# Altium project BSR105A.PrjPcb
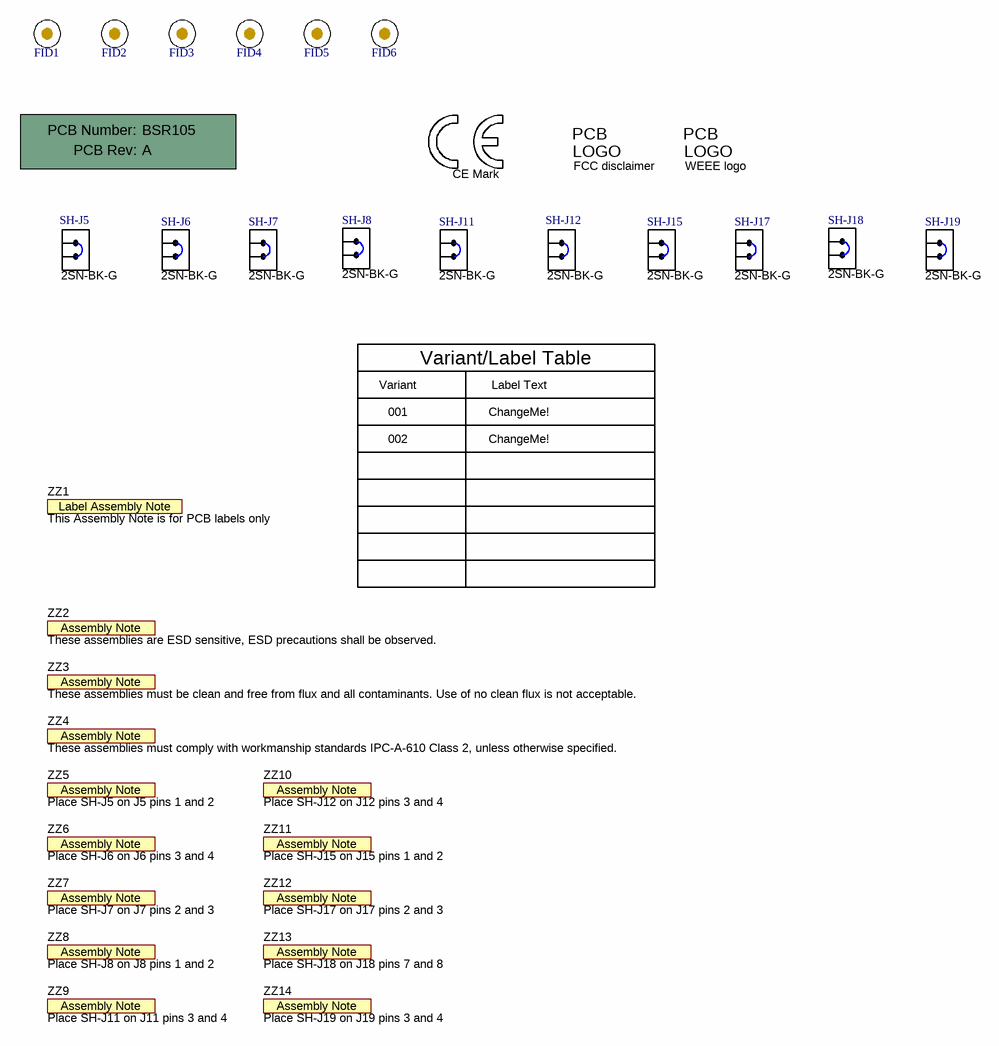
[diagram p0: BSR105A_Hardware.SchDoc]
CopyrightYear: 2019; EVM_Orderable: TPSM5D1806EVM; PCB_Layout: Jim McTeague; PCB_Rev: A; PRJ_Customer: Public Release; PRJ_Engineer: Jason Arrigo; PRJ_Number: BSR105; PRJ_Title: TPSM5D1806EVM; SCH_Rev: A; TechSupport: http://www.ti.com/support; TID: N/A
3 sheets, 167 parts. Net scope: global (net labels, ports and power ports of the same name join across sheets).
Board file: BSR105A.PcbDoc
Sheets:
  BSR105A_Hardware.SchDoc
  BSR105A_SHT2.schdoc
  BSR105A_SHT1.schdoc

## Sheet BSR105A_Hardware.SchDoc
size 431 x 279 mm; Date: Not shown in title block; ApprovedBy: Not shown in title block; CheckedBy: Not shown in title block; Author: Not shown in title block; CompanyName: Not shown in title block; Engineer: Not shown in title block; Organization: Not shown in title block; Address1: Not shown in title block; Address2: Not shown in title block; Address3: Not shown in title block; Address4: Not shown in title block; DocumentNumber: 3; Revision: Use project parameter SCH_Rev; SheetNumber: 3; SheetTotal: 3; PageSetup: Record=PageOptions¦CenterHorizontal=True¦CenterVertical=True¦PrintScale=1.00¦XCorrection=1.00¦YCorrection=1.00¦PrintKind=0¦BorderSize=5000000¦LeftOffset=0¦BottomOffset=0¦Orientation=2¦PaperLength=1000¦PaperWidth=1000¦Scale=100¦PaperSource=15¦PrintQuality=600¦MediaType=1¦DitherType=10¦PaperKind=Letter¦PrintScaleMode=1

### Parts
!PCB1  Printed Circuit Board  (value not drawn)  (mechanical)
FID1  Fiducial  [Fiducial10-30]  (value not drawn)
FID2  Fiducial  [Fiducial10-30]  (value not drawn)
FID3  Fiducial  [Fiducial10-30]  (value not drawn)
FID4  Fiducial  [Fiducial10-30]  (value not drawn)
FID5  Fiducial  [Fiducial10-30]  (value not drawn)
FID6  Fiducial  [Fiducial10-30]  (value not drawn)
Logo1  CE Mark  [CE_Mark_5mm]  (no BOM)
Logo3  FCC disclaimer  [FCC_disclaimer]  (no BOM)
Logo4  WEEE logo  [WEEE_Minimum]  (no BOM)
SH-J5  2SN-BK-G  [2SN-BK-G]
SH-J6  2SN-BK-G  [2SN-BK-G]
SH-J7  2SN-BK-G  [2SN-BK-G]
SH-J8  2SN-BK-G  [2SN-BK-G]
SH-J11  2SN-BK-G  [2SN-BK-G]
SH-J12  2SN-BK-G  [2SN-BK-G]
SH-J15  2SN-BK-G  [2SN-BK-G]
SH-J17  2SN-BK-G  [2SN-BK-G]
SH-J18  2SN-BK-G  [2SN-BK-G]
SH-J19  2SN-BK-G  [2SN-BK-G]
ZZ1  This Assembly Note is for PCB labels only  [AssemblyNoteLabel]  (no BOM)
ZZ2  These assemblies are ESD sensitive, ESD precautions shall be observed.  [AssemblyNote]  (no BOM)
ZZ3  These assemblies must be clean and free from flux and all contaminants. Use of no clean flux is not acceptable.  [AssemblyNote]  (no BOM)
ZZ4  These assemblies must comply with workmanship standards IPC-A-610 Class 2, unless otherwise specified.  [AssemblyNote]  (no BOM)
ZZ5  Place SH-J5 on J5 pins 1 and 2  [AssemblyNote]  (no BOM)
ZZ6  Place SH-J6 on J6 pins 3 and 4  [AssemblyNote]  (no BOM)
ZZ7  Place SH-J7 on J7 pins 2 and 3  [AssemblyNote]  (no BOM)
ZZ8  Place SH-J8 on J8 pins 1 and 2  [AssemblyNote]  (no BOM)
ZZ9  Place SH-J11 on J11 pins 3 and 4  [AssemblyNote]  (no BOM)
ZZ10  Place SH-J12 on J12 pins 3 and 4  [AssemblyNote]  (no BOM)
ZZ11  Place SH-J15 on J15 pins 1 and 2  [AssemblyNote]  (no BOM)
ZZ12  Place SH-J17 on J17 pins 2 and 3  [AssemblyNote]  (no BOM)
ZZ13  Place SH-J18 on J18 pins 7 and 8  [AssemblyNote]  (no BOM)
ZZ14  Place SH-J19 on J19 pins 3 and 4  [AssemblyNote]  (no BOM)

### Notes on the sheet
- Variant
- Variant/Label Table
- Label Text
- 001
- 002
- ChangeMe!

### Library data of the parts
!PCB1 = CMP-0003618-2: Manufacturer: Any; PartNumber: BSR105
FID1-FID6 = CMP-0077181-1: Fiducial mark.  There is nothing to buy or mount.
Logo1 = CMP-0074844-1: SymbolCreator: a0412235
Logo3 = CMP-0074847-1: FCC_disclaimer
Logo4 = CMP-0074769-1
SH-J5-SH-J8 SH-J11 SH-J12 SH-J15 SH-J17-SH-J19 = CMP-0003641-1: Shunt, 2mm, Gold plated, Black; Manufacturer: Samtec; Value: 1x2
ZZ1 = CMP-0003616-3
ZZ2 = CMP-0077236-1
ZZ3 = CMP-0077237-1
ZZ4 = CMP-0077238-1
ZZ5-ZZ14 = CMP-0003615-1: This Assembly Note will show in the PcbDoc and associated outputs

## Sheet BSR105A_SHT2.schdoc: TPSM5D1806 APL EVM Board
size 431 x 279 mm; REV: A; Number: TPSM5D1806 APL EVM Board; Date: Not shown in title block; ApprovedBy: Not shown in title block; CheckedBy: Not shown in title block; Author: Not shown in title block; CompanyName: Not shown in title block; DrawnBy: Jason Arrigo; Engineer: Not shown in title block; Organization: Not shown in title block; Address1: Not shown in title block; Address2: Not shown in title block; Address3: Not shown in title block; Address4: Not shown in title block; DocumentNumber: 1; Revision: Use project parameter SCH_Rev; SheetNumber: 2; SheetTotal: 3; PageSetup: Record=PageOptions¦CenterHorizontal=True¦CenterVertical=True¦PrintScale=0.96¦XCorrection=1.00¦YCorrection=1.00¦PrintKind=0¦BorderSize=5000000¦LeftOffset=0¦BottomOffset=0¦Orientation=2¦PaperLength=4318¦PaperWidth=2794¦Scale=100¦PaperSource=15¦PrintQuality=600¦MediaType=1¦DitherType=10¦PrintScaleMode=1¦PaperKind=Tabloid (11 x 17")¦PaperIndex=17
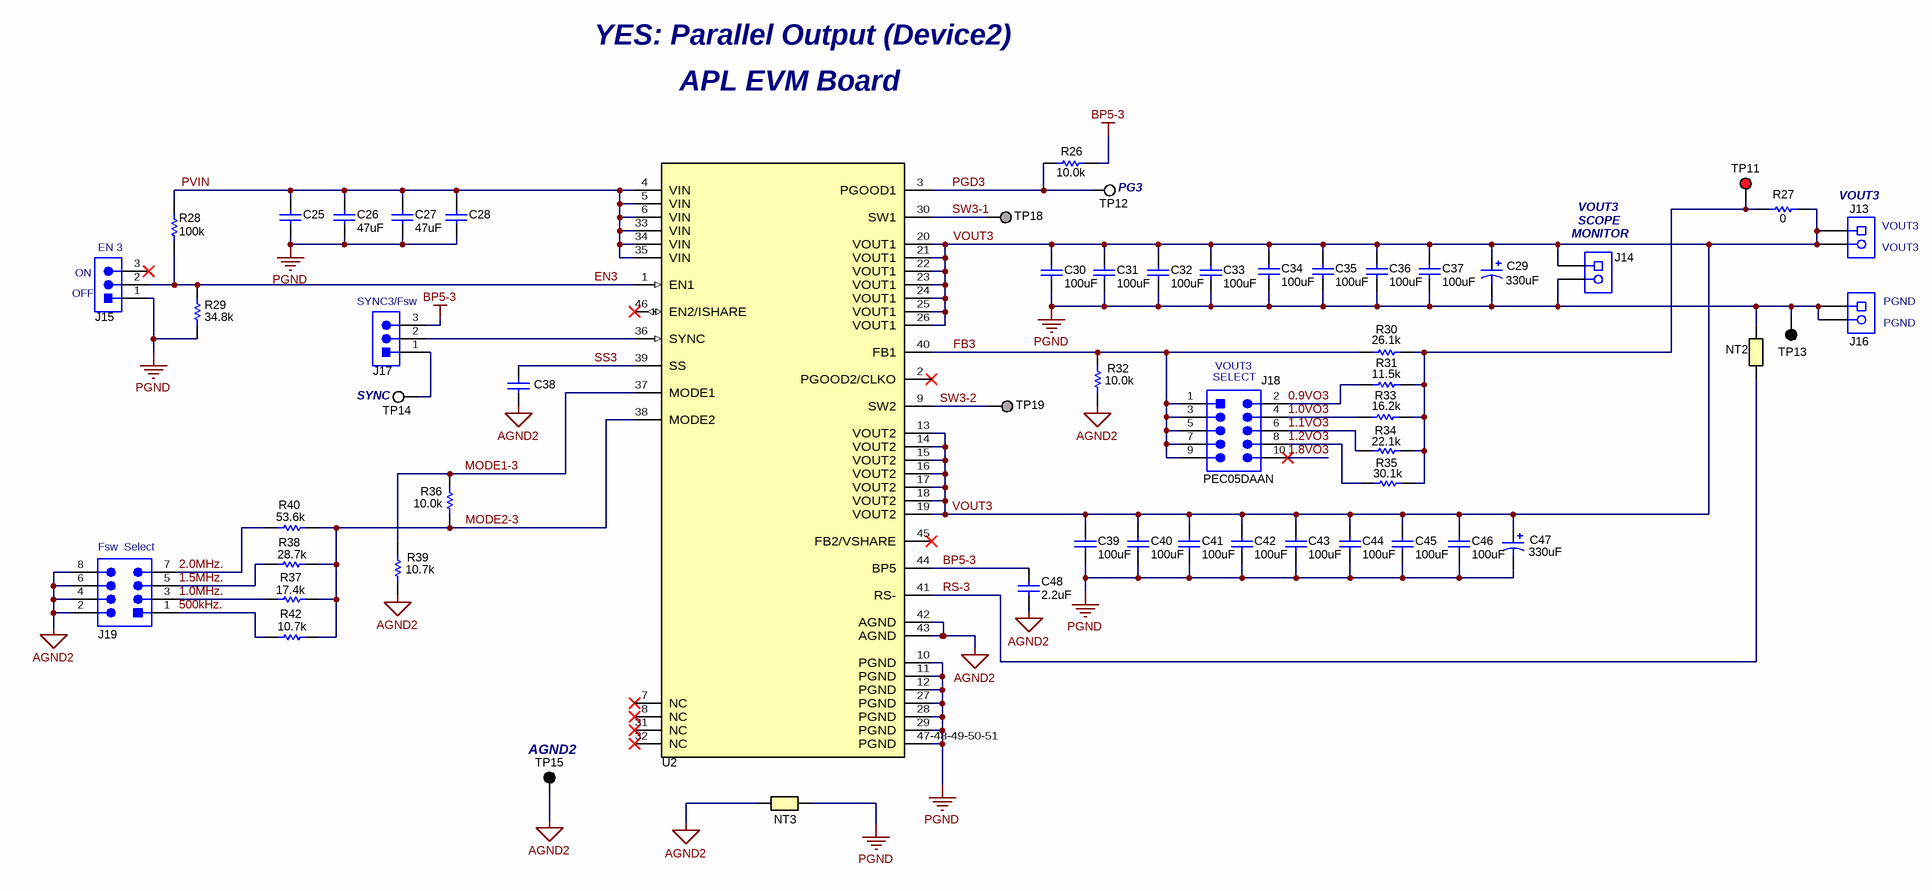
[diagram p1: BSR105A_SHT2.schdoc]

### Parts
C25  C3216X5R1E476M160AC  [1206_190]  (value not drawn)
C26  ValueDisplayed: 47uF  [1206_190]  (hidden comment: C3216X5R1E476M160AC)
C27  ValueDisplayed: 47uF  [1206_190]  (hidden comment: C3216X5R1E476M160AC)
C28  C3216X5R1E476M160AC  [1206_190]  (value not drawn)
C29  ValueDisplayed: 330uF  [7343-40]  (hidden comment: T520Y337M010ATE035)
C30  ValueDisplayed: 100uF  [1206_180]  (hidden comment: GRM31CR60J107ME39L)
C31  ValueDisplayed: 100uF  [1206_180]  (hidden comment: GRM31CR60J107ME39L)
C32  ValueDisplayed: 100uF  [1206_180]  (hidden comment: GRM31CR60J107ME39L)
C33  ValueDisplayed: 100uF  [1206_180]  (hidden comment: GRM31CR60J107ME39L)
C34  ValueDisplayed: 100uF  [1206_180]  (hidden comment: GRM31CR60J107ME39L)
C35  ValueDisplayed: 100uF  [1206_180]  (hidden comment: GRM31CR60J107ME39L)
C36  ValueDisplayed: 100uF  [1206_180]  (hidden comment: GRM31CR60J107ME39L)
C37  ValueDisplayed: 100uF  [1206_180]  (hidden comment: GRM31CR60J107ME39L)
C38  C1608X7R1H473K080AA  [0603]  (value not drawn)
C39  ValueDisplayed: 100uF  [1206_180]  (hidden comment: GRM31CR60J107ME39L)
C40  ValueDisplayed: 100uF  [1206_180]  (hidden comment: GRM31CR60J107ME39L)
C41  ValueDisplayed: 100uF  [1206_180]  (hidden comment: GRM31CR60J107ME39L)
C42  ValueDisplayed: 100uF  [1206_180]  (hidden comment: GRM31CR60J107ME39L)
C43  ValueDisplayed: 100uF  [1206_180]  (hidden comment: GRM31CR60J107ME39L)
C44  ValueDisplayed: 100uF  [1206_180]  (hidden comment: GRM31CR60J107ME39L)
C45  ValueDisplayed: 100uF  [1206_180]  (hidden comment: GRM31CR60J107ME39L)
C46  ValueDisplayed: 100uF  [1206_180]  (hidden comment: GRM31CR60J107ME39L)
C47  ValueDisplayed: 330uF  [7343-40]  (hidden comment: T520Y337M010ATE035)
C48  ValueDisplayed: 2.2uF  [0603]  (hidden comment: C1608X6S1C225K080AC)
J13  ED120/2DS  [On-Shore_ED120_2DS]  (value not drawn)
J14  310-43-102-41-001000  [Mill-max_310-43-102-41-001000]  (value not drawn)
J15  PEC03SAAN  [CONN_PEC03SAAN]  (value not drawn)
J16  ED120/2DS  [On-Shore_ED120_2DS]  (value not drawn)
J17  PEC03SAAN  [CONN_PEC03SAAN]  (value not drawn)
J18  PEC05DAAN  [CONN_PEC05DAAN]
J19  PEC04DAAN  [CONN_PEC04DAAN]  (value not drawn)
NT2  Net-Tie  [Net-Tie_10mil]  (value not drawn)  (net tie, no BOM)
NT3  Net-Tie  [Net-Tie_10mil]  (value not drawn)  (net tie, no BOM)
R26  ValueDisplayed: 10.0k  [0603]  (hidden comment: CRCW060310K0FKEA)
R27  ValueDisplayed: 0  [0603]  (hidden comment: CRCW06030000Z0EA)
R28  ValueDisplayed: 100k  [0603]  (hidden comment: CRCW0603100KFKEA)
R29  ValueDisplayed: 34.8k  [0603]  (hidden comment: CRCW060334K8FKEA)
R30  ValueDisplayed: 26.1k  [0603]  (hidden comment: CRCW060326K1FKEA)
R31  ValueDisplayed: 11.5k  [0603]  (hidden comment: CRCW060311K5FKEA)
R32  ValueDisplayed: 10.0k  [0603]  (hidden comment: CRCW060310K0FKEA)
R33  ValueDisplayed: 16.2k  [0603]  (hidden comment: CRCW060316K2FKEA)
R34  ValueDisplayed: 22.1k  [0603]  (hidden comment: CRCW060322K1FKEA)
R35  ValueDisplayed: 30.1k  [0603]  (hidden comment: CRCW060330K1FKEA)
R36  ValueDisplayed: 10.0k  [0603]  (hidden comment: CRCW060310K0FKEA)
R37  ValueDisplayed: 17.4k  [0603]  (hidden comment: CRCW060317K4FKEA)
R38  ValueDisplayed: 28.7k  [0603]  (hidden comment: CRCW060328K7FKEA)
R39  ValueDisplayed: 10.7k  [0603]  (hidden comment: CRCW060310K7FKEA)
R40  ValueDisplayed: 53.6k  [0603]  (hidden comment: CRCW060353K6FKEA)
R42  ValueDisplayed: 10.7k  [0603]  (hidden comment: CRCW060310K7FKEA)
TP11  5010  [Keystone5010]  (value not drawn)
TP12  5012  [Keystone5012]  (value not drawn)
TP13  5011  [Keystone5011]  (value not drawn)
TP14  5012  [Keystone5012]  (value not drawn)
TP15  5011  [Keystone5011]  (value not drawn)
TP18  TESTPOINT  [TP_25MIL-SMT]  (value not drawn)  (no BOM)
TP19  TESTPOINT  [TP_25MIL-SMT]  (value not drawn)  (no BOM)
U2  TPSM5D1806RDB  [RDB0051A-MFG]  (value not drawn)

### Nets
AGND2: C38.2 C48.2 J19.2 J19.4 J19.6 J19.8 NT3.1 R32.1 R39.1 TP15.1 U2.42(AGND) U2.43(AGND)
BP5-3: C48.1 J17.3 R26.2 U2.44(BP5)
PGND: C25.2 C26.2 C27.2 C28.2 C29.2(-) C30.2 C31.2 C32.2 C33.2 C34.2 C35.2 C36.2 C37.2 C39.2 C40.2 C41.2 C42.2 C43.2 C44.2 C45.2 C46.2 C47.2(-) J14.2 J15.1 J16.1 J16.2 NT2.2 NT3.2 R29.1 TP13.1 U2.10(PGND) U2.11(PGND) U2.12(PGND) U2.27(PGND) U2.28(PGND) U2.29(PGND) U2.47-48-49-50-51(PGND)
PVIN: C25.1 C26.1 C27.1 C28.1 R28.2 U2.4(VIN) U2.5(VIN) U2.6(VIN) U2.33(VIN) U2.34(VIN) U2.35(VIN)
0.9VO3: J18.2 R31.1
1.0MHz.: J19.3 R37.1
1.0VO3: J18.4 R33.1
1.1VO3: J18.6 R34.1
1.2VO3: J18.8 R35.1
1.5MHz.: J19.5 R38.1
1.8VO3: J18.10
2.0MHz.: J19.7 R40.1
500kHz.: J19.1 R42.1
EN3: J15.2 R28.1 R29.2 U2.1(EN1)
FB3: J18.1 J18.3 J18.5 J18.7 J18.9 R30.1 R32.2 U2.40(FB1)
MODE1-3: R36.2 R39.2 U2.37(MODE1)
MODE2-3: R36.1 R37.2 R38.2 R40.2 R42.2 U2.38(MODE2)
PGD3: R26.1 TP12.1 U2.3(PGOOD1)
RS-3: NT2.1 U2.41(RS-)
SS3: C38.1 U2.39(SS)
SW3-1: TP18.1 U2.30(SW1)
SW3-2: TP19.1 U2.9(SW2)
VOUT3: C29.1(+) C30.1 C31.1 C32.1 C33.1 C34.1 C35.1 C36.1 C37.1 C39.1 C40.1 C41.1 C42.1 C43.1 C44.1 C45.1 C46.1 C47.1(+) J13.1 J13.2 J14.1 R27.2 U2.13(VOUT2) U2.14(VOUT2) U2.15(VOUT2) U2.16(VOUT2) U2.17(VOUT2) U2.18(VOUT2) U2.19(VOUT2) U2.20(VOUT1) U2.21(VOUT1) U2.22(VOUT1) U2.23(VOUT1) U2.24(VOUT1) U2.25(VOUT1) U2.26(VOUT1)
NetJ17_1: J17.1 TP14.1
NetJ17_2: J17.2 U2.36(SYNC)
NetR27_1: R27.1 R30.2 R31.2 R33.2 R34.2 R35.2 TP11.1

Not connected (* = marked no-connect by the designer): J15 3*; U2 2(PGOOD2/CLKO)* 7(NC)* 8(NC)* 31(NC)* 32(NC)* 45(FB2/VSHARE)* 46(EN2/ISHARE)*

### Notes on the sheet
- YES: Parallel Output (Device2)
- APL EVM Board
- (near TP12) PG3
- (near J14) VOUT3
- VOUT3
- (near J15) ON
- (near J15) EN 3
- (near J14) MONITOR
- (near J14) SCOPE
- (near J13) VOUT3
- (near J15) OFF
- (near J17) SYNC3/Fsw
- (near J16) PGND
- (near TP14) SYNC
- (near J18) SELECT
- (near J18) VOUT3
- (near J19) Fsw  Select
- (near TP15) AGND2

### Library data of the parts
C25-C28 = CMP-0008656-2: CAP, CERM, 47 uF, 25 V, +/- 20%, X5R, 1206_190; Manufacturer: TDK; TaMin_C: -55°C; Polarized: N; SizeAreaWB_mm2: 10.92; Value1: Unknown; U/M: EA; Value: 47uF; TaMax_C: 85°C; SizeZ_mm: 1.9; SizeX_mm: 3.2; SizeY_mm: 1.6; Cap_Case: 1206; Value2: 25V; SizeArea_mm2: 5.12; Cap_F: 47µF; AEC Category: Q200
C29 C47 = CMP-0064986-2: CAP, Tantalum Polymer, 330 uF, 10 V,+/- 20%, 0.035 ohm, 7343-40 SMD; Manufacturer: Kemet; TaMin_C: -55°C; ESR_ohm: 0.035; Polarized: Y; SizeAreaWB_mm2: 58.59; Value: 330uF; TaMax_C: 105°C; SizeZ_mm: 4; SizeX_mm: 7.3; SizeY_mm: 4.3; Value2: 10V; SizeArea_mm2: 31.39; CompType: Capacitor; AEC Qualified: N; Cap_F: 330µF; AEC Category: Q200
C30-C33 C39-C42 = CMP-0008934-2: CAP, CERM, 100 uF, 6.3 V, +/- 20%, X5R, 1206; Manufacturer: MuRata; TaMin_C: -55°C; ESR_ohm: 3m; Polarized: N; SizeAreaWB_mm2: 10.92; Value1: 0.003 ohm; U/M: EA; Value: 100uF; TaMax_C: 85°C; SizeZ_mm: 1.8; SizeX_mm: 3.2; SizeY_mm: 1.6; Value2: 6.3V; SizeArea_mm2: 5.12; Cap_F: 100µF; AEC Category: Q200; Cap_Case: 1206
C34-C37 C43-C46 = CMP-0008934-2: CAP, CERM, 100 uF, 6.3 V, +/- 20%, X5R, 1206; Manufacturer: MuRata; TaMin_C: -55°C; ESR_ohm: 3m; Polarized: N; SizeAreaWB_mm2: 10.92; Value1: 0.003 ohm; U/M: EA; Value: 100uF; TaMax_C: 85°C; SizeZ_mm: 1.8; SizeX_mm: 3.2; SizeY_mm: 1.6; Cap_Case: 1206; Value2: 6.3V; SizeArea_mm2: 5.12; Cap_F: 100µF; AEC Category: Q200
C38 = CMP-0007049-4: CAP, CERM, 0.047 uF, 50 V, +/- 10%, X7R, 0603; Manufacturer: TDK; TaMin_C: -55°C; Polarized: N; SizeAreaWB_mm2: 4.68; Value1: 0.049007 ohm; U/M: EA; TaMax_C: 125°C; SizeZ_mm: 1; SizeX_mm: 1.6; SizeY_mm: 0.8; Value2: 50V; SizeArea_mm2: 1.28; Cap_F: 47nF; AEC Category: Q200; ESR_ohm: 0.049007; IRMS_A: 7.67528dA
C48 = CMP-0007026-4: CAP, CERM, 2.2 uF, 16 V, +/- 10%, X6S, 0603; Manufacturer: TDK; TaMin_C: -55°C; Polarized: N; SizeAreaWB_mm2: 4.68; Value1: 0.007674 ohm; U/M: EA; Value: 2.2uF; TaMax_C: 105°C; SizeZ_mm: 1; SizeX_mm: 1.6; SizeY_mm: 0.8; Value2: 16V; SizeArea_mm2: 1.28; Cap_F: 2.2µF; AEC Category: Q200; ESR_ohm: 7.674m; IRMS_A: 1.87823A
J13 J16 = CMP-0074910-1: Terminal Block, 5.08 mm, 2x1, Brass, TH; Manufacturer: On-Shore Technology; Cert_VDE: Y; CNHeader: False; Current_A: 15A; Green_Lifecycle: Not Set; Shrouded: N; Gender: Female; Green_REACh: Incomplete; Voltage_V: 300V; Row_Count: 1; Pitch_mm: 5.08; CT: True
J14 = CMP-0055017-1: Socket Strip, 2x1, 100mil, Black, Tin, TH; Manufacturer: Mill-Max; CNHeader: FALSE; CompType: Receptacle; Green_Lifecycle: Active; Green_REACh: Passed
J15 J17 = CMP-0002338-1: Header, 100mil, 3x1, Tin, TH; Manufacturer: Sullins Connector Solutions; CNHeader: TRUE; Current_A: 3A; Green_Lifecycle: Not Set; Shrouded: N; Gender: Male; Green_REACh: Incomplete; Voltage_V: 1.8kV; Row_Count: 1; Pitch_mm: 2.54; CT: FALSE; Cert_UL: Y
J18 = CMP-0054550-2: Header, 100mil, 5x2, Tin, TH; Manufacturer: Sullins Connector Solutions; Pitch_mm: 2.54; Gender: Male; Shrouded: N; Row_Count: 2; Current_A: 3A; Voltage_V: 1.8kV; Cert_UL: Y; Green_Lifecycle: Active; Green_REACh: Passed
J19 = CMP-0054542-2: Header, 100mil, 4x2, Tin, TH; Manufacturer: Sullins Connector Solutions; Current_A: 3A; Green_Lifecycle: Not Set; Shrouded: N; Gender: Male; Green_REACh: Incomplete; Voltage_V: 1.8kV; Row_Count: 2; RowSpacing_mm: 2.54; Cert_UL: Y
NT2 NT3 = CMP-0078142-3: Single point connection between nets.
R26 R32 R36 = CMP-0021998-4: RES, 10.0 k, 1%, 0.1 W, AEC-Q200 Grade 0, 0603; Manufacturer: Vishay-Dale; Power_W: 100mW; TempCo: 100 ppm/C; Value_Code: 10k0; Value: 10.0k; EIA_Code: E96; Res_ohm: 10k; SizeX_mm: 1.6; SizeY_mm: 0.8; SizeZ_mm: 1; Value2: 0.1W; SizeArea_mm2: 1.28; AEC Qualified: Y; VDC_V: 75V; AEC Category: Q200; AEC Grade: 0
R27 = CMP-0025697-4: RES, 0, 5%, 0.1 W, AEC-Q200 Grade 0, 0603; Manufacturer: Vishay-Dale; Power_W: 100mW; TempCo: 200 ppm/C; Value_Code: 0000; Value: 0; EIA_Code: E24; SizeX_mm: 1.6; SizeY_mm: 0.8; SizeZ_mm: 1; Value2: 0.1W; SizeArea_mm2: 1.28; AEC Qualified: Y; VDC_V: 75V; AEC Category: Q200
R28 = CMP-0021990-4: RES, 100 k, 1%, 0.1 W, AEC-Q200 Grade 0, 0603; Manufacturer: Vishay-Dale; Power_W: 100mW; TempCo: 100 ppm/C; Value: 100k; EIA_Code: E96; SizeX_mm: 1.6; SizeY_mm: 0.8; SizeZ_mm: 1; Value2: 0.1W; SizeArea_mm2: 1.28; AEC Qualified: Y; VDC_V: 75V; AEC Category: Q200; AEC Grade: 0
R29 = CMP-0022347-4: RES, 34.8 k, 1%, 0.1 W, AEC-Q200 Grade 0, 0603; Manufacturer: Vishay-Dale; Power_W: 100mW; TempCo: 100 ppm/C; Value_Code: 34k8; Value: 34.8k; EIA_Code: E96; SizeX_mm: 1.6; SizeY_mm: 0.8; SizeZ_mm: 1; Value2: 0.1W; SizeArea_mm2: 1.28; AEC Qualified: Y; VDC_V: 75V; AEC Category: Q200; AEC Grade: 0
R30 = CMP-0022248-4: RES, 26.1 k, 1%, 0.1 W, AEC-Q200 Grade 0, 0603; Manufacturer: Vishay-Dale; Power_W: 100mW; TempCo: 100 ppm/C; Value_Code: 26k1; Value: 26.1k; EIA_Code: E96; SizeX_mm: 1.6; SizeY_mm: 0.8; SizeZ_mm: 1; Value2: 0.1W; SizeArea_mm2: 1.28; AEC Qualified: Y; VDC_V: 75V; AEC Category: Q200; AEC Grade: 0
R31 = CMP-0022018-4: RES, 11.5 k, 1%, 0.1 W, AEC-Q200 Grade 0, 0603; Manufacturer: Vishay-Dale; Power_W: 100mW; TempCo: 100 ppm/C; Value_Code: 11k5; Value: 11.5k; EIA_Code: E96; SizeX_mm: 1.6; SizeY_mm: 0.8; SizeZ_mm: 1; Value2: 0.1W; SizeArea_mm2: 1.28; AEC Qualified: Y; VDC_V: 75V; AEC Category: Q200; AEC Grade: 0
R33 = CMP-0022079-4: RES, 16.2 k, 1%, 0.1 W, AEC-Q200 Grade 0, 0603; Manufacturer: Vishay-Dale; Power_W: 100mW; TempCo: 100 ppm/C; Value_Code: 16k2; Value: 16.2k; EIA_Code: E96; SizeX_mm: 1.6; SizeY_mm: 0.8; SizeZ_mm: 1; Value2: 0.1W; SizeArea_mm2: 1.28; AEC Qualified: Y; VDC_V: 75V; AEC Category: Q200; AEC Grade: 0
R34 = CMP-0022220-4: RES, 22.1 k, 1%, 0.1 W, AEC-Q200 Grade 0, 0603; Manufacturer: Vishay-Dale; Power_W: 100mW; TempCo: 100 ppm/C; Value_Code: 22k1; Value: 22.1k; EIA_Code: E96; SizeX_mm: 1.6; SizeY_mm: 0.8; SizeZ_mm: 1; Value2: 0.1W; SizeArea_mm2: 1.28; AEC Qualified: Y; VDC_V: 75V; AEC Category: Q200; AEC Grade: 0
R35 = CMP-0022324-4: RES, 30.1 k, 1%, 0.1 W, AEC-Q200 Grade 0, 0603; Manufacturer: Vishay-Dale; Power_W: 100mW; TempCo: 100 ppm/C; Value_Code: 30k1; Value: 30.1k; EIA_Code: E96; SizeX_mm: 1.6; SizeY_mm: 0.8; SizeZ_mm: 1; Value2: 0.1W; SizeArea_mm2: 1.28; AEC Qualified: Y; VDC_V: 75V; AEC Category: Q200; AEC Grade: 0
R37 = CMP-0022089-4: RES, 17.4 k, 1%, 0.1 W, AEC-Q200 Grade 0, 0603; Manufacturer: Vishay-Dale; Power_W: 100mW; TempCo: 100 ppm/C; Value_Code: 17k4; Value: 17.4k; EIA_Code: E96; SizeX_mm: 1.6; SizeY_mm: 0.8; SizeZ_mm: 1; Value2: 0.1W; SizeArea_mm2: 1.28; AEC Qualified: Y; VDC_V: 75V; AEC Category: Q200; AEC Grade: 0
R38 = CMP-0022261-4: RES, 28.7 k, 1%, 0.1 W, AEC-Q200 Grade 0, 0603; Manufacturer: Vishay-Dale; Power_W: 100mW; TempCo: 100 ppm/C; Value_Code: 28k7; Value: 28.7k; EIA_Code: E96; SizeX_mm: 1.6; SizeY_mm: 0.8; SizeZ_mm: 1; Value2: 0.1W; SizeArea_mm2: 1.28; AEC Qualified: Y; VDC_V: 75V; AEC Category: Q200; AEC Grade: 0
R39 R42 = CMP-0022001-4: RES, 10.7 k, 1%, 0.1 W, AEC-Q200 Grade 0, 0603; Manufacturer: Vishay-Dale; Power_W: 100mW; TempCo: 100 ppm/C; Value_Code: 10k7; Value: 10.7k; EIA_Code: E96; SizeX_mm: 1.6; SizeY_mm: 0.8; SizeZ_mm: 1; Value2: 0.1W; SizeArea_mm2: 1.28; AEC Qualified: Y; VDC_V: 75V; AEC Category: Q200; AEC Grade: 0
R40 = CMP-0022490-4: RES, 53.6 k, 1%, 0.1 W, AEC-Q200 Grade 0, 0603; Manufacturer: Vishay-Dale; Power_W: 100mW; TempCo: 100 ppm/C; Value_Code: 53k6; Value: 53.6k; EIA_Code: E96; SizeX_mm: 1.6; SizeY_mm: 0.8; SizeZ_mm: 1; Value2: 0.1W; SizeArea_mm2: 1.28; AEC Qualified: Y; VDC_V: 75V; AEC Category: Q200; AEC Grade: 0
TP11 = CMP-0055147-1: Test Point, Multipurpose, Red, TH; Manufacturer: Keystone; CNHeader: FALSE; ContactFinish: Silver; CT: TRUE; Green_Lifecycle: Active; Green_REACh: Passed
TP12 TP14 = CMP-0055149-1: Test Point, Multipurpose, White, TH; Manufacturer: Keystone; CNHeader: FALSE; ContactFinish: Silver; CT: TRUE; Green_Lifecycle: Active; Green_REACh: Passed
TP13 TP15 = CMP-0055148-1: Test Point, Multipurpose, Black, TH; Manufacturer: Keystone; CNHeader: FALSE; ContactFinish: Silver; CT: TRUE; Green_Lifecycle: Active; Green_REACh: Passed
TP18 TP19 = CMP-0078143-3: TEST POINT.  No entry in BOM.
U2 = CMP-0088389-1: 4.5-V to 18-V Input, Dual 6-A Output Power Module with Current Sharing; Manufacturer: Texas Instruments; AEC Qualified: No; Switching Frequency: 500/1000/1500/2250kHz; Max Duty Cycle: 80%; Output Voltage: 0.5-5.5V; Output Type: AdjustableProgrammable; TJmax_C: +150°C; Min Supply Voltage: 4.5V; Max Supply Voltage: 18V; Standoff Height: 0mm; Number Of Outputs: 2; Nominal Supply Current: 2500uA; SizeZ_mm: 1.9mm; Switching Topology: Buck; TaMin_C: -40°C; TaMax_C: +105°C

## Sheet BSR105A_SHT1.schdoc: TPSM5D1806 APL EVM Brd
size 431 x 279 mm; REV: E1; Number: TPSM5D1806 APL EVM Brd; Date: Not shown in title block; ApprovedBy: Not shown in title block; CheckedBy: Not shown in title block; Author: Not shown in title block; CompanyName: Not shown in title block; Engineer: Not shown in title block; Organization: Not shown in title block; Address1: Not shown in title block; Address2: Not shown in title block; Address3: Not shown in title block; Address4: Not shown in title block; DocumentNumber: 2; Revision: Use project parameter SCH_Rev; SheetNumber: 1; SheetTotal: 3; PageSetup: Record=PageOptions¦CenterHorizontal=True¦CenterVertical=True¦PrintScale=0.96¦XCorrection=1.00¦YCorrection=1.00¦PrintKind=0¦BorderSize=5000000¦LeftOffset=0¦BottomOffset=0¦Orientation=2¦PaperLength=4318¦PaperWidth=2794¦Scale=100¦PaperSource=15¦PrintQuality=600¦MediaType=1¦DitherType=10¦PrintScaleMode=1¦PaperKind=Tabloid (11 x 17")¦PaperIndex=17
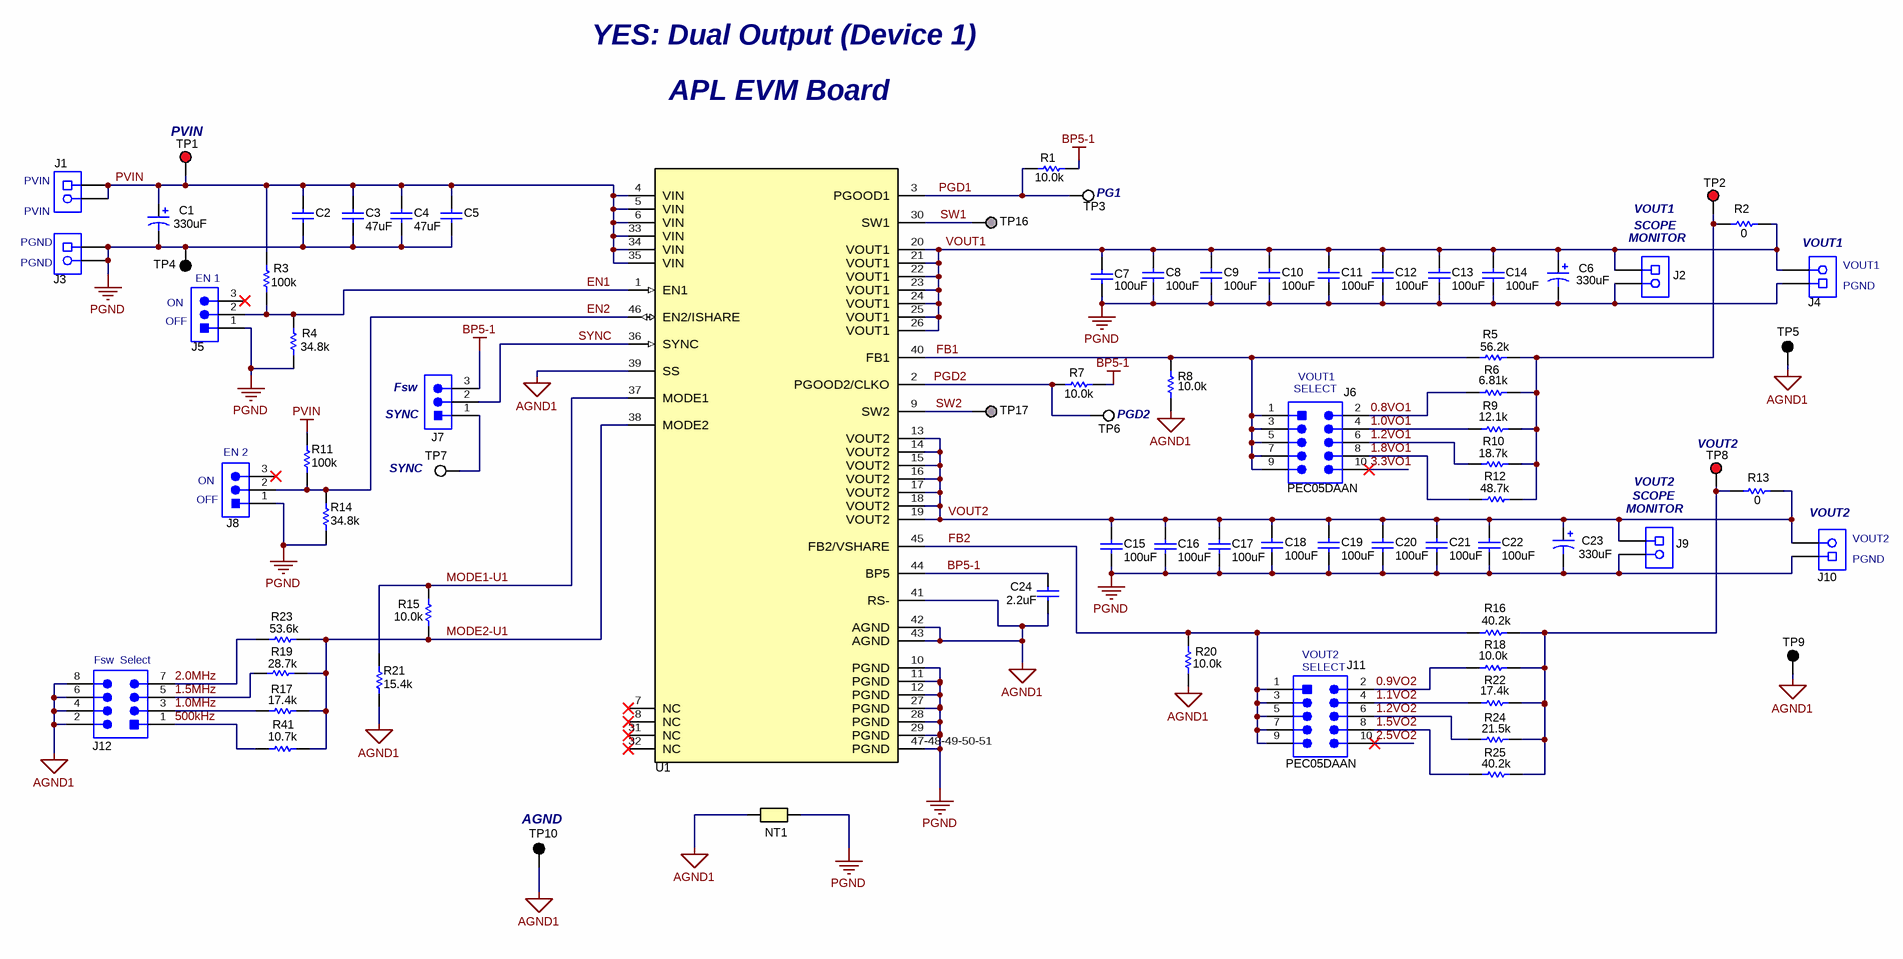
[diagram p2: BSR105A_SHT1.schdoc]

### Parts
C1  ValueDisplayed: 330uF  [SM_RADIAL_G]  (hidden comment: EEE-FC1E331P)
C2  C3216X5R1E476M160AC  [1206_190]  (value not drawn)
C3  ValueDisplayed: 47uF  [1206_190]  (hidden comment: C3216X5R1E476M160AC)
C4  ValueDisplayed: 47uF  [1206_190]  (hidden comment: C3216X5R1E476M160AC)
C5  C3216X5R1E476M160AC  [1206_190]  (value not drawn)
C6  ValueDisplayed: 330uF  [7343-40]  (hidden comment: T520Y337M010ATE035)
C7  ValueDisplayed: 100uF  [1206_180]  (hidden comment: GRM31CR60J107ME39L)
C8  ValueDisplayed: 100uF  [1206_180]  (hidden comment: GRM31CR60J107ME39L)
C9  ValueDisplayed: 100uF  [1206_180]  (hidden comment: GRM31CR60J107ME39L)
C10  ValueDisplayed: 100uF  [1206_180]  (hidden comment: GRM31CR60J107ME39L)
C11  ValueDisplayed: 100uF  [1206_180]  (hidden comment: GRM31CR60J107ME39L)
C12  ValueDisplayed: 100uF  [1206_180]  (hidden comment: GRM31CR60J107ME39L)
C13  ValueDisplayed: 100uF  [1206_180]  (hidden comment: GRM31CR60J107ME39L)
C14  ValueDisplayed: 100uF  [1206_180]  (hidden comment: GRM31CR60J107ME39L)
C15  ValueDisplayed: 100uF  [1206_180]  (hidden comment: GRM31CR60J107ME39L)
C16  ValueDisplayed: 100uF  [1206_180]  (hidden comment: GRM31CR60J107ME39L)
C17  ValueDisplayed: 100uF  [1206_180]  (hidden comment: GRM31CR60J107ME39L)
C18  ValueDisplayed: 100uF  [1206_180]  (hidden comment: GRM31CR60J107ME39L)
C19  ValueDisplayed: 100uF  [1206_180]  (hidden comment: GRM31CR60J107ME39L)
C20  ValueDisplayed: 100uF  [1206_180]  (hidden comment: GRM31CR60J107ME39L)
C21  ValueDisplayed: 100uF  [1206_180]  (hidden comment: GRM31CR60J107ME39L)
C22  ValueDisplayed: 100uF  [1206_180]  (hidden comment: GRM31CR60J107ME39L)
C23  ValueDisplayed: 330uF  [7343-40]  (hidden comment: T520Y337M010ATE035)
C24  ValueDisplayed: 2.2uF  [0603]  (hidden comment: C1608X6S1C225K080AC)
J1  ED120/2DS  [On-Shore_ED120_2DS]  (value not drawn)
J2  310-43-102-41-001000  [Mill-max_310-43-102-41-001000]  (value not drawn)
J3  ED120/2DS  [On-Shore_ED120_2DS]  (value not drawn)
J4  ED120/2DS  [On-Shore_ED120_2DS]  (value not drawn)
J5  PEC03SAAN  [CONN_PEC03SAAN]  (value not drawn)
J6  PEC05DAAN  [CONN_PEC05DAAN]
J7  PEC03SAAN  [CONN_PEC03SAAN]  (value not drawn)
J8  PEC03SAAN  [CONN_PEC03SAAN]  (value not drawn)
J9  310-43-102-41-001000  [Mill-max_310-43-102-41-001000]  (value not drawn)
J10  ED120/2DS  [On-Shore_ED120_2DS]  (value not drawn)
J11  PEC05DAAN  [CONN_PEC05DAAN]
J12  PEC04DAAN  [CONN_PEC04DAAN]  (value not drawn)
NT1  Net-Tie  [Net-Tie_10mil]  (value not drawn)  (net tie, no BOM)
R1  ValueDisplayed: 10.0k  [0603]  (hidden comment: CRCW060310K0FKEA)
R2  ValueDisplayed: 0  [0603]  (hidden comment: CRCW06030000Z0EA)
R3  ValueDisplayed: 100k  [0603]  (hidden comment: CRCW0603100KFKEA)
R4  ValueDisplayed: 34.8k  [0603]  (hidden comment: CRCW060334K8FKEA)
R5  ValueDisplayed: 56.2k  [0603]  (hidden comment: CRCW060356K2FKEA)
R6  ValueDisplayed: 6.81k  [0603]  (hidden comment: CRCW06036K81FKEA)
R7  ValueDisplayed: 10.0k  [0603]  (hidden comment: CRCW060310K0FKEA)
R8  ValueDisplayed: 10.0k  [0603]  (hidden comment: CRCW060310K0FKEA)
R9  ValueDisplayed: 12.1k  [0603]  (hidden comment: CRCW060312K1FKEA)
R10  ValueDisplayed: 18.7k  [0603]  (hidden comment: CRCW060318K7FKEA)
R11  ValueDisplayed: 100k  [0603]  (hidden comment: CRCW0603100KFKEA)
R12  ValueDisplayed: 48.7k  [0603]  (hidden comment: CRCW060348K7FKEA)
R13  ValueDisplayed: 0  [0603]  (hidden comment: CRCW06030000Z0EA)
R14  ValueDisplayed: 34.8k  [0603]  (hidden comment: CRCW060334K8FKEA)
R15  ValueDisplayed: 10.0k  [0603]  (hidden comment: CRCW060310K0FKEA)
R16  ValueDisplayed: 40.2k  [0603]  (hidden comment: CRCW060340K2FKEA)
R17  ValueDisplayed: 17.4k  [0603]  (hidden comment: CRCW060317K4FKEA)
R18  ValueDisplayed: 10.0k  [0603]  (hidden comment: CRCW060310K0FKEA)
R19  ValueDisplayed: 28.7k  [0603]  (hidden comment: CRCW060328K7FKEA)
R20  ValueDisplayed: 10.0k  [0603]  (hidden comment: CRCW060310K0FKEA)
R21  ValueDisplayed: 15.4k  [0603]  (hidden comment: CRCW060315K4FKEA)
R22  ValueDisplayed: 17.4k  [0603]  (hidden comment: CRCW060317K4FKEA)
R23  ValueDisplayed: 53.6k  [0603]  (hidden comment: CRCW060353K6FKEA)
R24  ValueDisplayed: 21.5k  [0603]  (hidden comment: CRCW060321K5FKEA)
R25  ValueDisplayed: 40.2k  [0603]  (hidden comment: CRCW060340K2FKEA)
R41  ValueDisplayed: 10.7k  [0603]  (hidden comment: CRCW060310K7FKEA)
TP1  5010  [Keystone5010]  (value not drawn)
TP2  5010  [Keystone5010]  (value not drawn)
TP3  5012  [Keystone5012]  (value not drawn)
TP4  5011  [Keystone5011]  (value not drawn)
TP5  5011  [Keystone5011]  (value not drawn)
TP6  5012  [Keystone5012]  (value not drawn)
TP7  5012  [Keystone5012]  (value not drawn)
TP8  5010  [Keystone5010]  (value not drawn)
TP9  5011  [Keystone5011]  (value not drawn)
TP10  5011  [Keystone5011]  (value not drawn)
TP16  TESTPOINT  [TP_25MIL-SMT]  (value not drawn)  (no BOM)
TP17  TESTPOINT  [TP_25MIL-SMT]  (value not drawn)  (no BOM)
U1  TPSM5D1806RDB  [RDB0051A-MFG]  (value not drawn)

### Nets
AGND1: C24.2 J12.2 J12.4 J12.6 J12.8 NT1.1 R8.1 R20.1 R21.1 TP5.1 TP9.1 TP10.1 U1.39(SS) U1.41(RS-) U1.42(AGND) U1.43(AGND)
BP5-1: C24.1 J7.3 R1.2 R7.2 U1.44(BP5)
PGND: C1.2(-) C2.2 C3.2 C4.2 C5.2 C6.2(-) C7.2 C8.2 C9.2 C10.2 C11.2 C12.2 C13.2 C14.2 C15.2 C16.2 C17.2 C18.2 C19.2 C20.2 C21.2 C22.2 C23.2(-) J2.2 J3.1 J3.2 J4.1 J5.1 J8.1 J9.2 J10.1 NT1.2 R4.1 R14.1 TP4.1 U1.10(PGND) U1.11(PGND) U1.12(PGND) U1.27(PGND) U1.28(PGND) U1.29(PGND) U1.47-48-49-50-51(PGND)
PVIN: C1.1(+) C2.1 C3.1 C4.1 C5.1 J1.1 J1.2 R3.2 R11.2 TP1.1 U1.4(VIN) U1.5(VIN) U1.6(VIN) U1.33(VIN) U1.34(VIN) U1.35(VIN)
0.8VO1: J6.2 R6.1
0.9VO2: J11.2 R18.1
1.0MHz: J12.3 R17.1
1.0VO1: J6.4 R9.1
1.1VO2: J11.4 R22.1
1.2VO1: J6.6 R10.1
1.2VO2: J11.6 R24.1
1.5MHz: J12.5 R19.1
1.5VO2: J11.8 R25.1
1.8VO1: J6.8 R12.1
2.0MHz: J12.7 R23.1
2.5VO2: J11.10
3.3VO1: J6.10
500kHz: J12.1 R41.1
EN1: J5.2 R3.1 R4.2 U1.1(EN1)
EN2: J8.2 R11.1 R14.2 U1.46(EN2/ISHARE)
FB1: J6.1 J6.3 J6.5 J6.7 J6.9 R5.1 R8.2 U1.40(FB1)
FB2: J11.1 J11.3 J11.5 J11.7 J11.9 R16.1 R20.2 U1.45(FB2/VSHARE)
MODE1-U1: R15.2 R21.2 U1.37(MODE1)
MODE2-U1: R15.1 R17.2 R19.2 R23.2 R41.2 U1.38(MODE2)
PGD1: R1.1 TP3.1 U1.3(PGOOD1)
PGD2: R7.1 TP6.1 U1.2(PGOOD2/CLKO)
SW1: TP16.1 U1.30(SW1)
SW2: TP17.1 U1.9(SW2)
SYNC: J7.2 U1.36(SYNC)
VOUT1: C6.1(+) C7.1 C8.1 C9.1 C10.1 C11.1 C12.1 C13.1 C14.1 J2.1 J4.2 R2.2 U1.20(VOUT1) U1.21(VOUT1) U1.22(VOUT1) U1.23(VOUT1) U1.24(VOUT1) U1.25(VOUT1) U1.26(VOUT1)
VOUT2: C15.1 C16.1 C17.1 C18.1 C19.1 C20.1 C21.1 C22.1 C23.1(+) J9.1 J10.2 R13.2 U1.13(VOUT2) U1.14(VOUT2) U1.15(VOUT2) U1.16(VOUT2) U1.17(VOUT2) U1.18(VOUT2) U1.19(VOUT2)
NetJ7_1: J7.1 TP7.1
NetR2_1: R2.1 R5.2 R6.2 R9.2 R10.2 R12.2 TP2.1
NetR13_1: R13.1 R16.2 R18.2 R22.2 R24.2 R25.2 TP8.1

Not connected (* = marked no-connect by the designer): J5 3*; J8 3*; U1 7(NC)* 8(NC)* 31(NC)* 32(NC)*

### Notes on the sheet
- YES: Dual Output (Device 1)
- (near TP1) PVIN
- APL EVM Board
- (near J1) PVIN
- PVIN
- (near TP3) PG1
- VOUT1
- SCOPE
- PGND
- (near J3) PGND
- EN 1
- (near J2) MONITOR
- (near J4) VOUT1
- (near J4) PGND
- OFF
- ON
- SYNC
- (near J7) Fsw
- (near TP6) PGD2
- (near J6) SELECT
- (near J6) VOUT1
- (near J8) ON
- (near J8) EN 2
- (near TP7) SYNC
- VOUT2
- (near TP8) VOUT2
- (near J8) OFF
- (near J9) MONITOR
- (near J10) VOUT2
- (near J10) PGND
- (near J12) Fsw  Select
- (near J11) VOUT2
- (near J11) SELECT
- (near TP10) AGND

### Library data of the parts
C1 = CMP-0010657-1: CAP, AL, 330 uF, 25 V, +/- 20%, 0.15 ohm, SMD; Manufacturer: Panasonic; TaMin_C: -40°C; ESR_ohm: 1.5d; Polarized: Y; SizeAreaWB_mm2: 172.2; U/M: EA; Value: 330uF; TaMax_C: 105°C; SizeZ_mm: 10.2; SizeX_mm: 12; SizeY_mm: 10.3; Cap_Case: G; Value2: 25V; SizeArea_mm2: 123.6; CompType: Capacitor; Cap_F: 330µF; IRMS_A: 6.7dA; AEC Category: Q200
C2-C5 = CMP-0008656-2: as C25 on sheet BSR105A_SHT2
C6 C23 = CMP-0064986-2: as C29 on sheet BSR105A_SHT2
C7-C22 = CMP-0008934-2: as C34 on sheet BSR105A_SHT2
C24 = CMP-0007026-4: as C48 on sheet BSR105A_SHT2
J1 J3 J4 J10 = CMP-0074910-1: as J13 on sheet BSR105A_SHT2
J2 J9 = CMP-0055017-1: as J14 on sheet BSR105A_SHT2
J5 J7 J8 = CMP-0002338-1: as J15 on sheet BSR105A_SHT2
J6 J11 = CMP-0054550-2: as J18 on sheet BSR105A_SHT2
J12 = CMP-0054542-2: as J19 on sheet BSR105A_SHT2
NT1 = CMP-0078142-3: Single point connection between nets.
R1 R7 R8 R15 R18 R20 = CMP-0021998-4: as R26 on sheet BSR105A_SHT2
R2 R13 = CMP-0025697-4: as R27 on sheet BSR105A_SHT2
R3 R11 = CMP-0021990-4: as R28 on sheet BSR105A_SHT2
R4 R14 = CMP-0022347-4: as R29 on sheet BSR105A_SHT2
R5 = CMP-0022499-4: RES, 56.2 k, 1%, 0.1 W, AEC-Q200 Grade 0, 0603; Manufacturer: Vishay-Dale; Power_W: 100mW; TempCo: 100 ppm/C; Value_Code: 56k2; Value: 56.2k; EIA_Code: E96; SizeX_mm: 1.6; SizeY_mm: 0.8; SizeZ_mm: 1; Value2: 0.1W; SizeArea_mm2: 1.28; AEC Qualified: Y; VDC_V: 75V; AEC Category: Q200; AEC Grade: 0
R6 = CMP-0022563-4: RES, 6.81 k, 1%, 0.1 W, AEC-Q200 Grade 0, 0603; Manufacturer: Vishay-Dale; Power_W: 100mW; TempCo: 100 ppm/C; Value_Code: 6k81; Value: 6.81k; EIA_Code: E96; SizeX_mm: 1.6; SizeY_mm: 0.8; SizeZ_mm: 1; Value2: 0.1W; SizeArea_mm2: 1.28; AEC Qualified: Y; VDC_V: 75V; AEC Category: Q200; AEC Grade: 0
R9 = CMP-0022030-4: RES, 12.1 k, 1%, 0.1 W, AEC-Q200 Grade 0, 0603; Manufacturer: Vishay-Dale; Power_W: 100mW; TempCo: 100 ppm/C; Value_Code: 12k1; Value: 12.1k; EIA_Code: E96; SizeX_mm: 1.6; SizeY_mm: 0.8; SizeZ_mm: 1; Value2: 0.1W; SizeArea_mm2: 1.28; AEC Qualified: Y; VDC_V: 75V; AEC Category: Q200; AEC Grade: 0
R10 = CMP-0022098-4: RES, 18.7 k, 1%, 0.1 W, AEC-Q200 Grade 0, 0603; Manufacturer: Vishay-Dale; Power_W: 100mW; TempCo: 100 ppm/C; Value_Code: 18k7; Value: 18.7k; EIA_Code: E96; SizeX_mm: 1.6; SizeY_mm: 0.8; SizeZ_mm: 1; Value2: 0.1W; SizeArea_mm2: 1.28; AEC Qualified: Y; VDC_V: 75V; AEC Category: Q200; AEC Grade: 0
R12 = CMP-0022443-4: RES, 48.7 k, 1%, 0.1 W, AEC-Q200 Grade 0, 0603; Manufacturer: Vishay-Dale; Power_W: 100mW; TempCo: 100 ppm/C; Value_Code: 48k7; Value: 48.7k; EIA_Code: E96; SizeX_mm: 1.6; SizeY_mm: 0.8; SizeZ_mm: 1; Value2: 0.1W; SizeArea_mm2: 1.28; AEC Qualified: Y; VDC_V: 75V; AEC Category: Q200; AEC Grade: 0
R16 R25 = CMP-0022410-4: RES, 40.2 k, 1%, 0.1 W, AEC-Q200 Grade 0, 0603; Manufacturer: Vishay-Dale; Power_W: 100mW; TempCo: 100 ppm/C; Value_Code: 40k2; Value: 40.2k; EIA_Code: E96; SizeX_mm: 1.6; SizeY_mm: 0.8; SizeZ_mm: 1; Value2: 0.1W; SizeArea_mm2: 1.28; AEC Qualified: Y; VDC_V: 75V; AEC Category: Q200; AEC Grade: 0
R17 R22 = CMP-0022089-4: as R37 on sheet BSR105A_SHT2
R19 = CMP-0022261-4: as R38 on sheet BSR105A_SHT2
R21 = CMP-0022067-4: RES, 15.4 k, 1%, 0.1 W, AEC-Q200 Grade 0, 0603; Manufacturer: Vishay-Dale; Power_W: 100mW; TempCo: 100 ppm/C; Value_Code: 15k4; Value: 15.4k; EIA_Code: E96; SizeX_mm: 1.6; SizeY_mm: 0.8; SizeZ_mm: 1; Value2: 0.1W; SizeArea_mm2: 1.28; AEC Qualified: Y; VDC_V: 75V; AEC Category: Q200; AEC Grade: 0
R23 = CMP-0022490-4: as R40 on sheet BSR105A_SHT2
R24 = CMP-0022213-4: RES, 21.5 k, 1%, 0.1 W, AEC-Q200 Grade 0, 0603; Manufacturer: Vishay-Dale; Power_W: 100mW; TempCo: 100 ppm/C; Value_Code: 21k5; Value: 21.5k; EIA_Code: E96; SizeX_mm: 1.6; SizeY_mm: 0.8; SizeZ_mm: 1; Value2: 0.1W; SizeArea_mm2: 1.28; AEC Qualified: Y; VDC_V: 75V; AEC Category: Q200; AEC Grade: 0
R41 = CMP-0022001-4: as R39 on sheet BSR105A_SHT2
TP1 TP2 TP8 = CMP-0055147-1: as TP11 on sheet BSR105A_SHT2
TP3 TP6 TP7 = CMP-0055149-1: as TP12 on sheet BSR105A_SHT2
TP4 TP5 TP9 TP10 = CMP-0055148-1: as TP13 on sheet BSR105A_SHT2
TP16 TP17 = CMP-0078143-3: TEST POINT.  No entry in BOM.
U1 = CMP-0088389-1: as U2 on sheet BSR105A_SHT2

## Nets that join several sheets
PGND: BSR105A_SHT2 (37 pins), BSR105A_SHT1 (42 pins)
PVIN: BSR105A_SHT2 (11 pins), BSR105A_SHT1 (16 pins)

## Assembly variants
001: not fitted C2 C5 C6 C9 C10 C13 C14 C17 C18 C21 C22 C23 C25 C28 C29 C32 C33 C36 C37 C38 C41 C42 C45 C46 C47 FID1 FID2 FID3 FID4 FID5 FID6 R3 R4 R11 R14 R28 R29 TP16 TP17 TP18 TP19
